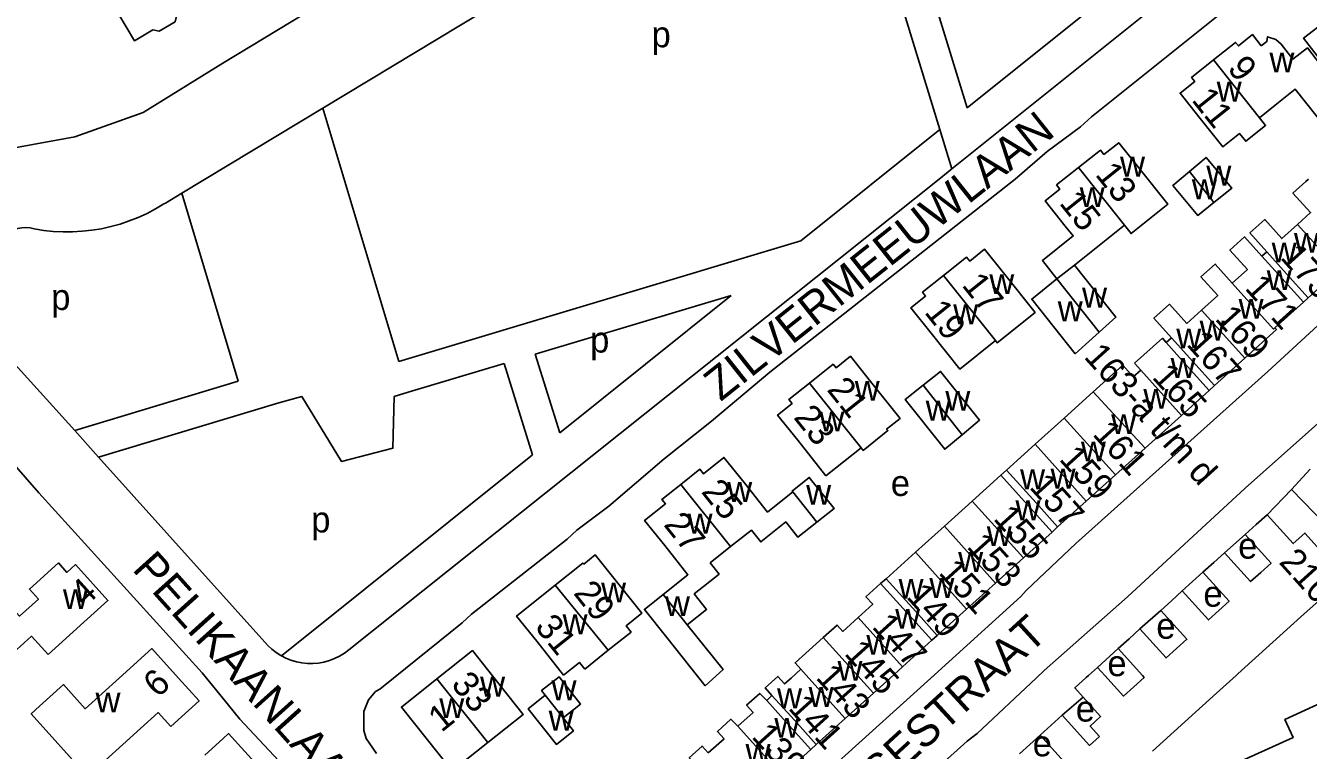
# Model space of a CAD drawing. Extents: x 161775 to 163181, y 382878 to 383925.
# Drawn here: x 162569.5 to 162768.1, y 383562.8 to 383675 of the extents above; entities that cross this region are included whole.
import ezdxf

# ---------------------------------------------------------------- set-up
doc = ezdxf.new("R2010")
doc.units = 0
for name, color, linetype in [('BLT_Basislijn', 7, 'Continuous'), ('BLT_Bebouwing', 7, 'Continuous'), ('BLT_Centroide', 7, 'Continuous'), ('BLT_Huisnummer', 7, 'Continuous'), ('BLT_Huisnummer_ tussenligend', 7, 'Continuous'), ('BLT_Huisnummer_reeks', 7, 'Continuous'), ('BLT_Onderdoorgang_en_onderverdeling', 7, 'Continuous'), ('BLT_Onderverdeling_panden', 7, 'Continuous'), ('BLT_Straatnaam', 7, 'Continuous')]:
    doc.layers.add(name, color=color, linetype=linetype)

msp = doc.modelspace()

# ---------------------------------------------------------------- linework, layer by layer
at = {"layer": 'BLT_Basislijn'}
for p, q in [((162695.27, 383710.43), (162711.05, 383658.91)), ((162615.46, 383662.23), (162691.4, 383708.01)), ((162712.92, 383652.82), (162768.39, 383697.27)), ((162747.45, 383688.05), (162715.25, 383662.27)), ((162600, 383669.19), (162629.33, 383686.98)), ((162710.57, 383677.56), (162715.25, 383662.27)), ((162593.62, 383649.06), (162615.46, 383662.23)), ((162627.26, 383623.04), (162615.46, 383662.23)), ((162711.05, 383658.91), (162689.52, 383641.7)), ((162711.05, 383658.91), (162712.92, 383652.82)), ((162710.93, 383651.22), (162712.92, 383652.82)), ((162619.52, 383578.37), (162710.93, 383651.22)), ((162591.09, 383647.54), (162593.62, 383649.06)), ((162593.62, 383649.06), (162602.39, 383619.95)), ((162627.26, 383623.04), (162689.52, 383641.7)), ((162648.36, 383624.14), (162678.73, 383633.24)), ((162678.73, 383633.24), (162652.16, 383611.95)), ((162566.35, 383624.21), (162577.05, 383612.32)), ((162648.36, 383624.14), (162652.16, 383611.95)), ((162628.7, 383618.25), (162643.57, 383622.71)), ((162643.57, 383622.71), (162647.97, 383608.59)), ((162602.39, 383619.95), (162577.05, 383612.32)), ((162608.65, 383616.61), (162580.74, 383608.21)), ((162577.05, 383612.32), (162580.74, 383608.21)), ((162580.74, 383608.21), (162606.94, 383579.08)), ((162647.97, 383608.59), (162609.1, 383577.44)), ((162768.38, 383606.35), (162765.52, 383603.22)), ((162765.52, 383603.22), (162782.64, 383585.42)), ((162758.33, 383596.23), (162755.13, 383593.42)), ((162751.77, 383590.39), (162748.59, 383587.5)), ((162745.27, 383584.49), (162742.02, 383581.62)), ((162738.65, 383578.57), (162735.44, 383575.67)), ((162729.97, 383568.26), (162733.25, 383571.05)), ((162726.56, 383565.18), (162723.38, 383562.3))]:
    msp.add_line(p, q, dxfattribs=at)
for points in [[(162626.44, 383574.02), (162637.05, 383582.56), (162638.49, 383583.91), (162653.34, 383595.54), (162654.82, 383596.89), (162659.77, 383600.62), (162668.36, 383607.94), (162675.68, 383613.76), (162684.73, 383621.34), (162722.73, 383651.25), (162727.65, 383655.52), (162732.82, 383659.35), (162734.51, 383660.88), (162769.87, 383689.21), (162778.48, 383695.66), (162782.77, 383696.15), (162785.83, 383692.92)], [(162564.03, 383655.39), (162577.08, 383657.78), (162587.65, 383661.55), (162600, 383669.19)], [(162805.75, 383661.89), (162761.83, 383621.46), (162732.09, 383594.83), (162724.39, 383587.57), (162723.59, 383586.62), (162709.65, 383574.02)], [(162725.94, 383574.02), (162727.2, 383575.2), (162740.08, 383586.57), (162758.35, 383603.41), (162788.21, 383630), (162790.45, 383632.28), (162805.73, 383646.24), (162819.54, 383658.33), (162821.71, 383658.73), (162824.34, 383655.92)], [(162570.77, 383643.55), (162572.25, 383643.31), (162573.74, 383643.16), (162575.24, 383643.08), (162576.73, 383643.08), (162578.23, 383643.17), (162579.71, 383643.33), (162581.19, 383643.57), (162582.65, 383643.89), (162584.09, 383644.29), (162585.51, 383644.77), (162586.9, 383645.32), (162588.27, 383645.94), (162589.59, 383646.64), (162590.88, 383647.4), (162591.09, 383647.54)], [(162570.77, 383643.55), (162570.14, 383643.68), (162569.5, 383643.74), (162568.86, 383643.71), (162568.22, 383643.61), (162567.6, 383643.43), (162567.01, 383643.17), (162566.45, 383642.85), (162565.94, 383642.45), (162565.48, 383642), (162565.08, 383641.49), (162564.75, 383640.94), (162564.48, 383640.35), (162564.3, 383639.76)], [(162608.65, 383616.61), (162612.23, 383617.58), (162618.37, 383607.55), (162626.34, 383609.6), (162626.55, 383617.58), (162628.7, 383618.25)], [(162571.49, 383602.7), (162563.33, 383611.96), (162559.83, 383615.2), (162559.03, 383615.74), (162556.77, 383616.56), (162553.14, 383616.56), (162550.13, 383615.17)], [(162597.46, 383574.02), (162596.79, 383574.85), (162571.49, 383602.7)], [(162761.72, 383599.29), (162765.52, 383603.22)], [(162606.94, 383579.08), (162607.57, 383578.49), (162608.25, 383577.96), (162608.98, 383577.5), (162609.1, 383577.44)], [(162609.1, 383577.44), (162609.75, 383577.11), (162610.55, 383576.78), (162611.38, 383576.54), (162612.23, 383576.37), (162613.09, 383576.28), (162613.95, 383576.27), (162614.81, 383576.34), (162615.66, 383576.49), (162616.49, 383576.72), (162617.3, 383577.03), (162618.08, 383577.4), (162618.82, 383577.85), (162619.52, 383578.37)], [(162643.92, 383522.1), (162642.03, 383524.09), (162614.49, 383554.61), (162610.89, 383558.85), (162602.61, 383567.68), (162600, 383570.89), (162597.46, 383574.02)], [(162623.8, 383562.33), (162622.18, 383564.66), (162621.83, 383565.9), (162621.83, 383568.86), (162622.55, 383570.67), (162623.65, 383571.96), (162624.32, 383572.31), (162626.44, 383574.02)], [(162631.01, 383482.55), (162628.85, 383484.67), (162628.29, 383485.46), (162650.35, 383505.87), (162665.82, 383519.46), (162667.7, 383521.72), (162674.07, 383527.56), (162692.83, 383544.06), (162715.29, 383564.27), (162716.81, 383565.45), (162725.94, 383574.02)], [(162709.65, 383574.02), (162666.66, 383535.19), (162666.44, 383534.79), (162661.91, 383530.65), (162660.47, 383529.64), (162658.37, 383529.25), (162656.59, 383529.18), (162655, 383529.77), (162653.22, 383531.07)], [(162770.77, 383573.84), (162772.03, 383571.07), (162764.47, 383567.61), (162765.74, 383564.84), (162758.22, 383561.4)]]:
    msp.add_lwpolyline(points, dxfattribs=at)
at = {"layer": 'BLT_Bebouwing'}
for p, q in [((162731.88, 383637.95), (162739.62, 383644.12)), ((162760.93, 383639.31), (162761.7, 383639.99)), ((162772.59, 383636.94), (162768.09, 383632.89)), ((162767.34, 383632.2), (162762.91, 383628.22)), ((162767.34, 383632.2), (162768.09, 383632.89)), ((162746.11, 383625.97), (162746.92, 383626.68)), ((162742.16, 383621.68), (162741.2, 383622.74)), ((162758.26, 383623.54), (162753.56, 383619.3)), ((162734.78, 383618.31), (162730.29, 383614.26)), ((162752.76, 383618.54), (162748.46, 383614.67)), ((162752.76, 383618.54), (162753.56, 383619.3)), ((162730.29, 383614.26), (162725.79, 383610.2)), ((162748.46, 383614.67), (162742.86, 383609.62)), ((162742.86, 383609.62), (162738.22, 383605.45)), ((162720.49, 383605.42), (162721.36, 383606.2)), ((162738.22, 383605.45), (162733.72, 383601.4)), ((162716.06, 383601.42), (162711.74, 383597.53)), ((162733.72, 383601.4), (162729.28, 383597.4)), ((162761.72, 383599.29), (162760.02, 383597.76)), ((162711.74, 383597.53), (162707.25, 383593.48)), ((162728.43, 383596.62), (162723.98, 383592.61)), ((162728.43, 383596.62), (162729.28, 383597.4)), ((162760.02, 383597.76), (162758.33, 383596.23)), ((162723.98, 383592.61), (162719.68, 383588.73)), ((162753.45, 383591.91), (162751.77, 383590.39)), ((162755.13, 383593.42), (162753.45, 383591.91)), ((162701.86, 383588.66), (162702.72, 383589.39)), ((162719.68, 383588.73), (162715.18, 383584.67)), ((162746.93, 383585.99), (162745.27, 383584.49)), ((162748.59, 383587.5), (162746.93, 383585.99)), ((162766.97, 383583.49), (162770.24, 383586.45)), ((162715.18, 383584.67), (162710.65, 383580.59)), ((162763.71, 383580.55), (162766.97, 383583.49)), ((162709.8, 383579.86), (162710.65, 383580.59)), ((162740.34, 383580.1), (162738.65, 383578.57)), ((162742.02, 383581.62), (162740.34, 383580.1)), ((162760.44, 383577.59), (162763.71, 383580.55)), ((162709.8, 383579.86), (162705.25, 383575.76)), ((162757.18, 383574.65), (162760.44, 383577.59)), ((162703.32, 383574.02), (162700.74, 383571.69)), ((162705.25, 383575.76), (162703.32, 383574.02)), ((162734.04, 383574.4), (162733.68, 383574.08)), ((162735.44, 383575.67), (162734.04, 383574.4)), ((162753.91, 383571.69), (162756.91, 383574.4)), ((162756.91, 383574.4), (162757.18, 383574.65)), ((162684.22, 383570.56), (162685.04, 383571.34)), ((162700.74, 383571.69), (162696.38, 383567.76)), ((162750.62, 383568.72), (162753.91, 383571.69)), ((162729.97, 383568.26), (162728.26, 383566.72)), ((162747.32, 383565.74), (162750.62, 383568.72)), ((162696.38, 383567.76), (162691.91, 383563.73)), ((162728.26, 383566.72), (162726.56, 383565.18)), ((162743.96, 383562.71), (162747.32, 383565.74)), ((162691.06, 383562.98), (162686.6, 383558.96)), ((162691.06, 383562.98), (162691.91, 383563.73))]:
    msp.add_line(p, q, dxfattribs=at)
for points in [[(162588.33, 383690.65), (162593.12, 383682.67), (162595.7, 383678.38), (162592.89, 383676.69), (162592.62, 383675.6), (162590.15, 383674.12), (162589.15, 383674.37), (162586.31, 383672.67), (162583.74, 383676.96), (162579.12, 383684.65), (162582.74, 383686.85), (162582.39, 383687.43), (162584.51, 383688.72), (162582.44, 383692.12), (162585.57, 383694.02), (162586.15, 383693.08), (162588.63, 383694.59), (162585.84, 383699.16), (162590.16, 383701.79), (162594.56, 383694.55), (162588.33, 383690.65)], [(162770.37, 383669.19), (162767.38, 383673.06), (162771.11, 383675.95), (162767.27, 383680.77), (162767.74, 383681.15), (162767.24, 383681.78), (162770.39, 383684.29), (162770.89, 383683.67), (162772.7, 383685.11)], [(162760.81, 383671.87), (162759.46, 383673.61), (162757.28, 383671.87), (162756.85, 383672.41), (162753.43, 383669.69)], [(162770.37, 383669.19), (162770.01, 383668.91), (162767.96, 383671.55), (162765.73, 383669.82), (162763.92, 383672.14), (162763.08, 383672.84), (162761.8, 383673.28), (162761.69, 383672.54), (162760.81, 383671.87)], [(162753.43, 383669.69), (162750.02, 383666.97), (162750.51, 383666.36), (162748.24, 383664.55), (162751.36, 383660.64), (162754.88, 383656.23), (162757.46, 383658.29), (162758.41, 383657.1), (162761.5, 383659.56), (162760.55, 383660.74)], [(162760.55, 383660.74), (162763.25, 383662.9), (162766.07, 383665.15), (162771.1, 383658.85), (162775.59, 383662.44)], [(162739.62, 383644.12), (162740.65, 383642.82), (162746.33, 383647.36), (162741.86, 383652.97), (162738.74, 383656.88), (162736.46, 383655.06), (162735.91, 383655.75), (162732.52, 383653.05)], [(162749.7, 383652.43), (162752.28, 383654.59), (162756.26, 383649.84), (162753.48, 383647.61)], [(162732.52, 383653.05), (162729.13, 383650.35), (162729.64, 383649.71), (162727.35, 383647.88), (162730.47, 383643.97), (162731.69, 383642.44), (162726.92, 383638.64), (162729.18, 383635.8)], [(162753.48, 383647.61), (162750.97, 383645.62), (162747.1, 383650.25), (162749.7, 383652.43)], [(162768.13, 383651.26), (162767.7, 383650.86), (162765.72, 383649.09), (162768.45, 383646.06), (162766.43, 383644.24)], [(162761.7, 383639.99), (162759.07, 383642.91), (162761.35, 383644.97), (162763.99, 383642.04), (162766.43, 383644.24)], [(162760.93, 383639.31), (162758.23, 383642.31), (162755.97, 383640.27), (162758.67, 383637.28), (162756.32, 383635.16)], [(162719.65, 383626.25), (162719.91, 383625.92), (162725.78, 383630.6), (162721.09, 383636.48), (162717.98, 383640.39), (162715.67, 383638.55), (162715.18, 383639.16), (162711.62, 383636.32)], [(162731.88, 383637.95), (162738.31, 383629.9), (162735.73, 383627.57)], [(162756.32, 383635.16), (162753.68, 383638.09), (162751.48, 383636.11), (162754.08, 383633.22), (162751.58, 383630.97)], [(162711.62, 383636.32), (162708.37, 383633.73), (162708.84, 383633.14), (162706.56, 383631.33), (162709.68, 383627.42), (162714.13, 383621.84), (162719.65, 383626.25)], [(162735.73, 383627.57), (162732.01, 383624.22), (162725.27, 383632.68), (162729.18, 383635.8)], [(162746.92, 383626.68), (162744.19, 383629.72), (162746.63, 383631.88), (162749.3, 383628.91), (162751.58, 383630.97)], [(162762.91, 383628.22), (162763.16, 383627.95), (162758.26, 383623.54)], [(162746.11, 383625.97), (162745.53, 383626.62), (162741.2, 383622.74)], [(162698.84, 383609.67), (162699.17, 383609.26), (162702.99, 383612.31), (162702.8, 383612.55), (162704.87, 383614.2), (162700.32, 383619.91), (162697.2, 383623.82), (162694.96, 383622.04), (162694.51, 383622.6), (162690.85, 383619.68)], [(162742.16, 383621.68), (162740.99, 383620.63), (162739.36, 383622.44), (162734.78, 383618.31)], [(162690.85, 383619.68), (162687.67, 383617.15), (162688.16, 383616.53), (162685.9, 383614.73), (162689.02, 383610.82), (162693.4, 383605.33), (162698.84, 383609.67)], [(162708.45, 383619.34), (162711.16, 383621.49), (162717.19, 383613.94), (162714.48, 383611.68)], [(162714.48, 383611.68), (162711.79, 383609.42), (162705.66, 383617.11), (162708.45, 383619.34)], [(162721.36, 383606.2), (162725.79, 383610.2)], [(162688.25, 383602.82), (162684.35, 383599.72), (162680.72, 383604.27), (162677.6, 383608.18), (162674.42, 383605.65), (162673.87, 383606.35), (162670.93, 383604)], [(162670.93, 383604), (162668, 383601.66), (162668.53, 383600.99), (162665.31, 383598.42), (162668.43, 383594.51), (162672.02, 383590.01), (162668.19, 383586.96)], [(162688.25, 383602.82), (162688.15, 383602.95), (162690.82, 383605.08), (162694.65, 383600.26), (162691.98, 383598.14)], [(162720.49, 383605.42), (162716.06, 383601.42)], [(162678.62, 383594.36), (162681.85, 383596.93), (162683.31, 383595.1), (162687.18, 383598.18), (162689.07, 383595.81), (162691.98, 383598.14)], [(162773.75, 383589.62), (162770.93, 383592.75), (162767.57, 383596.46), (162765.76, 383594.82), (162761.72, 383599.29)], [(162758.33, 383596.23), (162762.33, 383591.79), (162760.75, 383590.37)], [(162671.93, 383582.26), (162674.92, 383584.65), (162673.01, 383587.04), (162676.86, 383590.11), (162675.48, 383591.85), (162678.62, 383594.36)], [(162659.68, 383578.32), (162663.21, 383581.14), (162662.44, 383582.1), (162664.87, 383584.04), (162657.66, 383593.09), (162655.88, 383591.67), (162655.76, 383591.82), (162651.44, 383588.37)], [(162702.72, 383589.39), (162707.25, 383593.48)], [(162760.75, 383590.37), (162759.17, 383588.94), (162755.13, 383593.42)], [(162572.93, 383577.64), (162578.49, 383582.65), (162582.2, 383586), (162577.17, 383591.58), (162575.84, 383590.38), (162574.54, 383591.83), (162570.04, 383587.78), (162571.43, 383586.25), (162568.5, 383583.6), (162565.12, 383587.35), (162561.4, 383584), (162560.22, 383582.94), (162563.02, 383579.83), (162565.09, 383577.54), (162567.17, 383579.42), (162568.08, 383578.42), (162570.37, 383580.48), (162572.93, 383577.64)], [(162751.77, 383590.39), (162755.83, 383585.9), (162754.24, 383584.46)], [(162651.44, 383588.37), (162645.48, 383583.62), (162648.6, 383579.71), (162652.77, 383574.48)], [(162701.86, 383588.66), (162699.58, 383586.61), (162700.65, 383585.43), (162698.38, 383583.37)], [(162668.19, 383586.96), (162665.29, 383584.65), (162668.77, 383580.27), (162674.71, 383572.83), (162677.47, 383575.32), (162671.93, 383582.26)], [(162754.24, 383584.46), (162752.64, 383583.01), (162748.59, 383587.5)], [(162745.27, 383584.49), (162749.3, 383580.03), (162747.69, 383578.58)], [(162698.38, 383583.37), (162696, 383581.23), (162695.12, 383582.21), (162692.99, 383580.29)], [(162692.99, 383580.29), (162688.63, 383576.35), (162689.51, 383575.38)], [(162747.69, 383578.58), (162746.08, 383577.13), (162742.02, 383581.62)], [(162593.12, 383574.02), (162589.02, 383578.58), (162583.96, 383574.02)], [(162641.01, 383564.05), (162646.53, 383568.38), (162641.76, 383574.37), (162638.64, 383578.28), (162633.15, 383573.9)], [(162656.04, 383575.41), (162659.68, 383578.32)], [(162738.65, 383578.57), (162742.42, 383574.4)], [(162652.77, 383574.48), (162655.22, 383576.43), (162656.04, 383575.41)], [(162583.96, 383574.02), (162578.69, 383569.28), (162575.34, 383573), (162571.62, 383569.65), (162570.32, 383568.47), (162579.04, 383558.79), (162590, 383568.67), (162591.94, 383566.52)], [(162591.94, 383566.52), (162596.32, 383570.47), (162593.12, 383574.02)], [(162649.93, 383571.36), (162649.37, 383572.07), (162652.07, 383574.21), (162655.4, 383570), (162652.7, 383567.86)], [(162685.04, 383571.34), (162684.01, 383572.49), (162685.97, 383574.26), (162687, 383573.11), (162688.01, 383574.02)], [(162688.01, 383574.02), (162689.51, 383575.38)], [(162733.68, 383574.08), (162731.93, 383572.5), (162733.25, 383571.05)], [(162736.58, 383574.4), (162735.44, 383575.67)], [(162741.06, 383572.67), (162739.46, 383571.22), (162736.58, 383574.4)], [(162742.42, 383574.4), (162742.67, 383574.12), (162741.06, 383572.67)], [(162633.15, 383573.9), (162627.66, 383569.52), (162635.52, 383559.67), (162641.01, 383564.05)], [(162652.7, 383567.86), (162654.3, 383565.84), (162651.66, 383563.75), (162647.29, 383569.26), (162649.93, 383571.36)], [(162684.22, 383570.56), (162683.14, 383571.64), (162681.1, 383569.81), (162682.12, 383568.67), (162679.76, 383566.55)], [(162733.25, 383571.05), (162735.94, 383568.06), (162734.31, 383566.59), (162735.76, 383564.99)], [(162735.76, 383564.99), (162734.2, 383563.58), (162729.97, 383568.26)], [(162679.76, 383566.55), (162678.67, 383567.64), (162676.59, 383565.76), (162677.62, 383564.62), (162675.18, 383562.42)], [(162597.18, 383562.08), (162600, 383564.62), (162600.89, 383565.43), (162605.93, 383559.84), (162598.84, 383553.46), (162601.96, 383550), (162599.87, 383547.88)], [(162726.56, 383565.18), (162730.73, 383560.57), (162729.13, 383559.13)], [(162675.18, 383562.42), (162674.22, 383563.48), (162672.22, 383561.68), (162673.18, 383560.62), (162670.74, 383558.42)]]:
    msp.add_lwpolyline(points, dxfattribs=at)
at = {"layer": 'BLT_Onderdoorgang_en_onderverdeling'}
for points in [[(162768.09, 383632.89), (162764.75, 383636.6), (162761.7, 383639.99)], [(162767.34, 383632.2), (162763.99, 383635.92), (162760.93, 383639.31)], [(162752.76, 383618.54), (162749.41, 383622.26), (162746.11, 383625.97)], [(162753.56, 383619.3), (162750.21, 383623.02), (162746.92, 383626.68)], [(162729.28, 383597.4), (162725.94, 383601.12), (162721.36, 383606.2)], [(162728.43, 383596.62), (162725.08, 383600.33), (162720.49, 383605.42)], [(162709.8, 383579.86), (162701.86, 383588.66)], [(162710.65, 383580.59), (162707.31, 383584.3), (162702.72, 383589.39)], [(162691.06, 383562.98), (162687.71, 383566.69), (162684.22, 383570.56)], [(162691.91, 383563.73), (162688.56, 383567.44), (162685.04, 383571.34)]]:
    msp.add_lwpolyline(points, dxfattribs=at)
at = {"layer": 'BLT_Onderverdeling_panden'}
for p, q in [((162760.55, 383660.74), (162753.43, 383669.69)), ((162739.62, 383644.12), (162732.52, 383653.05)), ((162749.7, 383652.43), (162753.48, 383647.61)), ((162729.18, 383635.8), (162731.88, 383637.95)), ((162711.62, 383636.32), (162719.65, 383626.25)), ((162729.18, 383635.8), (162735.73, 383627.57)), ((162751.58, 383630.97), (162758.26, 383623.54)), ((162748.46, 383614.67), (162742.16, 383621.68)), ((162690.85, 383619.68), (162698.84, 383609.67)), ((162708.45, 383619.34), (162714.48, 383611.68)), ((162742.86, 383609.62), (162734.78, 383618.31)), ((162738.22, 383605.45), (162730.29, 383614.26)), ((162733.72, 383601.4), (162725.79, 383610.2)), ((162670.93, 383604), (162678.62, 383594.36)), ((162691.98, 383598.14), (162688.25, 383602.82)), ((162716.06, 383601.42), (162723.98, 383592.61)), ((162711.74, 383597.53), (162719.68, 383588.73)), ((162707.25, 383593.48), (162715.18, 383584.67)), ((162659.68, 383578.32), (162651.44, 383588.37)), ((162671.93, 383582.26), (162668.19, 383586.96)), ((162705.25, 383575.76), (162698.38, 383583.37)), ((162700.74, 383571.69), (162692.99, 383580.29)), ((162690.73, 383574.02), (162689.51, 383575.38)), ((162696.38, 383567.76), (162690.73, 383574.02)), ((162633.15, 383573.9), (162641.01, 383564.05)), ((162649.93, 383571.36), (162652.7, 383567.86)), ((162686.6, 383558.96), (162679.76, 383566.55))]:
    msp.add_line(p, q, dxfattribs=at)
for points in [[(162766.43, 383644.24), (162772.82, 383637.14), (162772.59, 383636.94)], [(162756.32, 383635.16), (162762.72, 383628.04), (162762.91, 383628.22)]]:
    msp.add_lwpolyline(points, dxfattribs=at)

# ---------------------------------------------------------------- texts
at = {"layer": 'BLT_Centroide'}
for s, p in [('p', (162666.39, 383671.65)), ('w', (162762.09, 383667.75)), ('w', (162753.92, 383663.25)), ('w', (162738.95, 383651.64)), ('w', (162752.32, 383650.25)), ('w', (162732.7, 383646.91)), ('w', (162750.07, 383648.12)), ('w', (162765.88, 383639.84)), ('w', (162762.43, 383638.35)), ('w', (162718.7, 383633.45)), ('w', (162761.66, 383634.06)), ('p', (162573.41, 383630.99)), ('w', (162733.07, 383631.35)), ('w', (162713.11, 383628.78)), ('w', (162729.3, 383629.23)), ('w', (162757.31, 383629.62)), ('w', (162747.66, 383625.04)), ('w', (162751.28, 383626.25)), ('p', (162656.88, 383624.4)), ('w', (162746.78, 383620.48)), ('w', (162697.86, 383616.95)), ('w', (162711.89, 383615.39)), ('w', (162742.56, 383615.69)), ('w', (162708.85, 383613.88)), ('w', (162692.38, 383612.2)), ('w', (162737.58, 383611.78)), ('w', (162732.89, 383607.56)), ('w', (162723.47, 383603.24)), ('w', (162728.19, 383603.34)), ('w', (162678.11, 383601.28)), ('w', (162690.34, 383600.83)), ('e', (162703.45, 383602.2)), ('w', (162722.75, 383598.44)), ('p', (162613.68, 383596.56)), ('w', (162671.97, 383596.38)), ('w', (162718.31, 383594.44)), ('e', (162757.24, 383592.5)), ('w', (162713.88, 383590.44)), ('w', (162658.58, 383585.73)), ('w', (162704.65, 383586.29)), ('w', (162709.42, 383586.41)), ('e', (162751.85, 383585.06)), ('w', (162575.23, 383584.69)), ('w', (162668.48, 383583.61)), ('w', (162704.12, 383581.66)), ('w', (162652.61, 383580.81)), ('e', (162744.56, 383580.1)), ('w', (162699.66, 383577.62)), ('w', (162695.19, 383573.59)), ('e', (162736.99, 383574.31)), ('w', (162639.84, 383571.14)), ('w', (162650.9, 383570.57)), ('w', (162685.83, 383569.33)), ('w', (162690.72, 383569.55)), ('w', (162580.28, 383568.69)), ('w', (162633.52, 383567.81)), ('e', (162732.09, 383567.28)), ('w', (162650.46, 383565.88)), ('w', (162685.41, 383564.77)), ('e', (162725.42, 383561.9)), ('w', (162680.95, 383560.73))]:
    msp.add_text(s, height=4, dxfattribs=at).set_placement(p)
at = {"layer": 'BLT_Huisnummer'}
for s, rotation, p in [('9', 308.5686, (162755.45, 383668.34)), ('11', 308.5686, (162749.92, 383663.46)), ('13', 308.5721, (162734.99, 383651.92)), ('15', 308.5721, (162729.42, 383647.5)), ('17', 308.5757, (162714.33, 383634.8)), ('171', 311.9929, (162758.14, 383634.29)), ('19', 308.5757, (162708.53, 383630.61)), ('165', 311.998, (162743.77, 383620.52)), ('21', 308.5802, (162693.43, 383618.62)), ('23', 308.5802, (162688.27, 383614.32)), ('161', 312.0496, (162734.56, 383611.68)), ('25', 308.5675, (162673.97, 383602.82)), ('157', 312.0496, (162724.76, 383603.51)), ('155', 312.0496, (162719.19, 383598.62)), ('27', 308.5675, (162668.15, 383597.72)), ('4', 42.0322, (162578.6, 383584.9)), ('29', 308.574, (162654.18, 383587.12)), ('149', 312.0528, (162705.73, 383586.52)), ('31', 308.574, (162648.2, 383581.89)), ('147', 312.0528, (162700.39, 383581.88)), ('6', 42.0306, (162589.92, 383570.84)), ('33', 308.5784, (162635.22, 383573.01)), ('141', 312.0406, (162687.43, 383569.29)), ('1', 38.5626, (162633.84, 383565.51)), ('139', 312.0406, (162681.75, 383564.88))]:
    msp.add_text(s, height=4, rotation=rotation, dxfattribs=at).set_placement(p)
at = {"layer": 'BLT_Huisnummer_ tussenligend'}
for s, rotation, p in [('173', 311.9929, (162763.64, 383639.04)), ('169', 311.9966, (162753.52, 383629.55)), ('167', 311.9966, (162749.11, 383625.6)), ('159', 312.0496, (162729.38, 383607.83)), ('153', 312.0528, (162715.07, 383594.29)), ('151', 312.0528, (162710.73, 383590.24)), ('145', 312.0516, (162696.11, 383577.73)), ('143', 312.0516, (162691.7, 383574.01))]:
    msp.add_text(s, height=4, rotation=rotation, dxfattribs=at).set_placement(p)
at = {"layer": 'BLT_Huisnummer_reeks'}
for s, rotation, p in [('163-a t/m d', 311.998, (162733.22, 383623.66)), ('210b', 312.0994, (162763.43, 383591.88))]:
    msp.add_text(s, height=4, rotation=rotation, dxfattribs=at).set_placement(p)
at = {"layer": 'BLT_Straatnaam'}
for s, height, rotation, p in [('ZILVERMEEUWLAAN', 5, 38.5186, (162677.09, 383616.73)), ('PELIKAANLAAN', 4.9999, 311.9288, (162585.82, 383590.8)), ('TONGELRESESTRAAT', 5, 42.4828, (162674.77, 383531.77))]:
    msp.add_text(s, height=height, rotation=rotation, dxfattribs=at).set_placement(p)

doc.saveas('drawing.dxf')
